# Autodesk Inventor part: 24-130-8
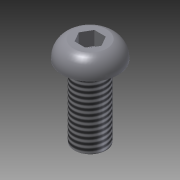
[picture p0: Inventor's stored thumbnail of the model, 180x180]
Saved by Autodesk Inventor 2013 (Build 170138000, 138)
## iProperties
Created: 2004-10
Part Number: 24-130-8
Material: Stahl (hohe Festigk., niedr. Legier.)
Document SubType Name: Modeling
Designer: Autodesk, Inc.
Manufacturer: Standard
Standards Organization: Custom
Description: SCREW, PARKER IPS, BUTTON HEAD, M8X30
Catalog Web Link: http://www.parker.com/ead/cm1.asp?cmid=809
Vendor: PARKER IPS
Mass: 10.8823 g
Surface Area: 9.37524 cm^2
Volume: 1.38805 cm^3
Density: 7.84 g/cm^3
CAGE: 1LJX3
Dept. ID: Product Design
Description #2: ---
Finish #1: ---
Finish #2: ---
Material ID: ---
Project Number: ---
Author: Autodesk, Inc.
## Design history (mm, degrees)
derived "2X-YYY-ZZ IPS Screws.ipt"
body "Solid1"
tag "TaggingFeature2"
feature "Solid1::2X-YYY-ZZ IPS Screws.ipt" dims "ScaleForDerivedMember" = 10
